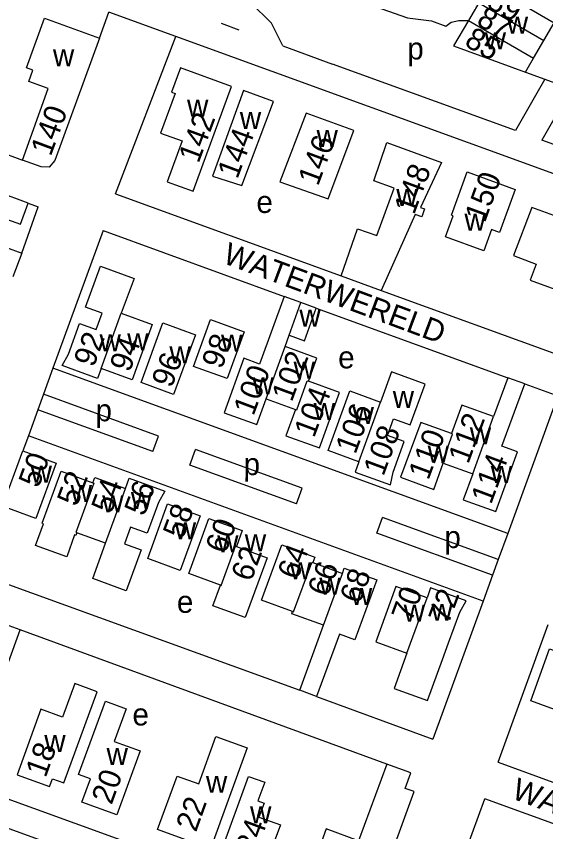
# Model space of a CAD drawing. Extents: x 154320 to 156262, y 382651 to 384180.
# Drawn here: x 156007.7 to 156103.4, y 383033.1 to 383180.7 of the extents above; entities that cross this region are included whole.
import ezdxf

# ---------------------------------------------------------------- set-up
doc = ezdxf.new("R2010")
doc.units = 0
for name, color, linetype in [('BLT_Basislijn', 7, 'Continuous'), ('BLT_Bebouwing', 7, 'Continuous'), ('BLT_Centroide', 7, 'Continuous'), ('BLT_Huisnummer', 7, 'Continuous'), ('BLT_Huisnummer_ tussenligend', 7, 'Continuous'), ('BLT_Onderverdeling_panden', 7, 'Continuous'), ('BLT_Plantopo', 7, 'Continuous'), ('BLT_Straatnaam', 7, 'Continuous')]:
    doc.layers.add(name, color=color, linetype=linetype)

msp = doc.modelspace()

# ---------------------------------------------------------------- linework, layer by layer
at = {"layer": 'BLT_Basislijn'}
for p, q in [((156022.72, 383176.68), (156024.45, 383181.39)), ((156036.57, 383176.99), (156024.45, 383181.39)), ((156047.98, 383178.16), (156044.79, 383179.32)), ((156025.65, 383148.51), (156036.57, 383176.99)), ((156118.43, 383147.22), (156036.57, 383176.99)), ((156055.87, 383175.29), (156064.86, 383172.02)), ((155963.09, 383171.24), (156008.81, 383154.64)), ((156099.75, 383170.56), (156103.25, 383169.28)), ((156103.25, 383169.28), (156097.97, 383159.98)), ((156103.25, 383169.28), (156108.02, 383167.55)), ((156108.02, 383167.55), (156102.73, 383158.25)), ((156025.65, 383148.51), (156066.46, 383133.71)), ((156009.83, 383146.86), (156011.63, 383146.15)), ((156008.68, 383137.82), (156011.63, 383146.15)), ((156023.38, 383141.88), (156014.32, 383116.97)), ((156023.38, 383141.88), (156056.14, 383129.95)), ((156073.69, 383131.02), (156108, 383118.56)), ((156061.92, 383127.86), (156096.6, 383115.25)), ((156014.32, 383116.97), (156012.62, 383112.28)), ((156096.56, 383087.08), (156014.32, 383116.97)), ((156099.63, 383114.14), (156105.61, 383111.98)), ((156012.62, 383112.28), (156011.59, 383109.46)), ((156033.43, 383104.71), (156012.62, 383112.28)), ((156105.61, 383111.98), (156096.56, 383087.08)), ((156011.59, 383109.46), (156009.88, 383104.76)), ((156032.41, 383101.89), (156011.59, 383109.46)), ((156009.88, 383104.76), (156008.87, 383102.02)), ((156092.11, 383074.86), (156009.88, 383104.76)), ((156032.41, 383101.89), (156033.43, 383104.71)), ((156039.1, 383099.45), (156040.13, 383102.27)), ((156059.4, 383095.26), (156040.13, 383102.27)), ((156058.38, 383092.45), (156039.1, 383099.45)), ((156058.38, 383092.45), (156059.4, 383095.26)), ((156072.92, 383087.16), (156073.95, 383089.98)), ((156094.85, 383082.38), (156073.95, 383089.98)), ((156093.82, 383079.56), (156072.92, 383087.16)), ((156096.56, 383087.08), (156094.85, 383082.38)), ((156094.85, 383082.38), (156093.82, 383079.56)), ((156000.83, 383079.85), (156058.97, 383058.73)), ((156093.82, 383079.56), (156092.11, 383074.86)), ((156092.11, 383074.86), (156083.02, 383049.84)), ((156094.81, 383045.68), (156103.86, 383070.59)), ((156074.68, 383045.34), (156008.37, 383069.63)), ((156062.01, 383057.59), (156083.02, 383049.84)), ((156082.33, 383011.38), (156092.41, 383039.1))]:
    msp.add_line(p, q, dxfattribs=at)
for points in [[(156053.63, 383189.1), (156063.31, 383185.56), (156068.94, 383184.05), (156070.37, 383183.18), (156078.47, 383180.38), (156082.76, 383179.81), (156085.39, 383178.84), (156086.36, 383179.59), (156087.7, 383179.88), (156089.47, 383179.91)], [(156055.87, 383175.29), (156053.84, 383179.39), (156050.04, 383183.15)], [(156097.97, 383159.98), (156064.86, 383172.02)], [(156200.85, 383089.67), (156203.15, 383094.62), (156204.46, 383100.24), (156204.4, 383106.02), (156203.12, 383111.67), (156200.54, 383116.84), (156196.98, 383121.3), (156192.54, 383124.94), (156187.68, 383127.36), (156102.73, 383158.25)], [(155988.35, 383045.55), (156070.59, 383015.65)], [(156094.81, 383045.68), (156114.6, 383038.49)], [(156150.87, 383017.85), (156092.41, 383039.1)], [(155997.68, 383036.84), (156068.88, 383010.95)]]:
    msp.add_lwpolyline(points, dxfattribs=at)
at = {"layer": 'BLT_Bebouwing'}
for p, q in [((156022.72, 383176.68), (156014.69, 383154.59)), ((156072.36, 383150.9), (156074.71, 383157.79)), ((156074.71, 383157.79), (156084.58, 383154.19)), ((156084.58, 383154.19), (156080.78, 383146.07)), ((156009.83, 383146.86), (155990.99, 383153.67)), ((156076.01, 383149.57), (156072.36, 383150.9)), ((156072.91, 383141), (156076.01, 383149.57)), ((156080.78, 383146.07), (156081.53, 383145.8)), ((156081.53, 383145.8), (156081.01, 383144.35)), ((156079.84, 383144.77), (156073.9, 383131.59)), ((156081.01, 383144.35), (156079.84, 383144.77)), ((156066.46, 383133.71), (156069.38, 383142.21)), ((156069.38, 383142.21), (156072.91, 383141)), ((156008.68, 383137.82), (156007.09, 383133.49)), ((156066.46, 383133.71), (156073.69, 383131.02)), ((156073.9, 383131.59), (156073.69, 383131.02)), ((156059.18, 383128.85), (156056.14, 383129.95)), ((156061.92, 383127.86), (156059.18, 383128.85)), ((156056.29, 383120.88), (156057.04, 383122.94)), ((156096.6, 383115.25), (156094, 383108.24)), ((156099.63, 383114.14), (156096.6, 383115.25)), ((156052.86, 383111.47), (156058.2, 383109.54)), ((156005.23, 383092.02), (156008.87, 383102.02)), ((156084.9, 383099.82), (156090.23, 383097.88)), ((156023.83, 383085.31), (156018.63, 383087.19)), ((156061.33, 383081.8), (156066.67, 383079.86)), ((156058.97, 383058.73), (156063.24, 383070.47)), ((156062.01, 383057.59), (156058.97, 383058.73))]:
    msp.add_line(p, q, dxfattribs=at)
for points in [[(156091.34, 383183.11), (156089.47, 383179.91)], [(156008.81, 383154.64), (156013.47, 383167.57), (156009.96, 383168.83), (156010.7, 383170.88), (156009.55, 383171.3), (156012.81, 383180.32), (156022.72, 383176.68)], [(156089.47, 383179.91), (156086.77, 383175.28), (156099.75, 383170.56)], [(156103.08, 383176.26), (156104.95, 383179.47)], [(156101.21, 383173.06), (156103.08, 383176.26)], [(156100.07, 383171.11), (156101.21, 383173.06)], [(156099.75, 383170.56), (156100.07, 383171.11)], [(156014.69, 383154.59), (156013.66, 383153.36), (156012.19, 383153.42), (156008.81, 383154.64)], [(155990.99, 383153.67), (155989.19, 383148.68), (155994.83, 383146.63), (155994.42, 383145.49), (156005.07, 383141.61), (156005.93, 383143.96), (156008.44, 383143.06), (156009.83, 383146.86)], [(156001.61, 383137.9), (156005.74, 383138.89), (156008.68, 383137.82)], [(156023.06, 383116.91), (156022.39, 383115.13), (156016.02, 383117.5), (156017.11, 383119.5), (156019.14, 383125.07), (156022.14, 383123.98), (156023.2, 383126.92), (156020.21, 383128.02), (156022.92, 383135.43), (156028.99, 383133.21), (156026.67, 383126.93)], [(156056.14, 383129.95), (156051.67, 383117.74), (156048.84, 383118.78), (156045.3, 383108.92), (156051.17, 383106.78), (156052.86, 383111.47)], [(156057.04, 383122.94), (156059.79, 383121.95), (156061.92, 383127.86)], [(156026.67, 383126.93), (156032.29, 383124.88), (156028.67, 383114.88), (156023.06, 383116.91)], [(156060.53, 383114.62), (156062.04, 383118.79), (156056.29, 383120.88)], [(156069.62, 383100.05), (156068.95, 383098.18), (156075.38, 383095.86), (156075.84, 383098.16), (156077.84, 383103.71), (156074.83, 383104.79), (156075.93, 383107.8), (156078.94, 383106.71), (156081.63, 383114.11), (156075.55, 383116.32), (156073.57, 383110.86)], [(156058.2, 383109.54), (156056.47, 383104.76), (156062.5, 383102.58), (156066.14, 383112.57), (156060.53, 383114.62)], [(156069.62, 383100.05), (156064.08, 383102.07), (156068.03, 383112.88), (156073.57, 383110.86)], [(156090.23, 383097.88), (156088.52, 383093.18), (156094.41, 383091.06), (156098.32, 383101.85), (156095.49, 383102.89), (156099.63, 383114.14)], [(156094, 383108.24), (156088.26, 383110.31), (156086.37, 383105.14)], [(156086.37, 383105.14), (156080.83, 383107.15), (156077.16, 383097.24), (156083.19, 383095.03), (156084.9, 383099.82)], [(156008.87, 383102.02), (156014.88, 383099.83), (156011.22, 383089.81), (156005.23, 383092.02)], [(156018.63, 383087.19), (156018.46, 383086.74), (156018.23, 383086.83), (156016.82, 383082.85), (156011.19, 383084.91), (156012.62, 383088.85), (156012.4, 383088.94), (156015.81, 383098.35), (156021.55, 383096.26)], [(156027.44, 383095.19), (156028.12, 383097.07), (156034.54, 383094.74), (156033.42, 383092.68), (156031.38, 383087.11), (156028.37, 383088.21), (156027.29, 383085.23), (156030.29, 383084.14), (156027.59, 383076.73), (156021.53, 383078.93), (156023.83, 383085.31)], [(156021.55, 383096.26), (156021.89, 383097.2), (156027.44, 383095.19)], [(156044.6, 383077.72), (156038.91, 383079.83), (156042.53, 383089.79), (156048.53, 383087.59), (156047.49, 383084.71)], [(156047.49, 383084.71), (156053.05, 383082.68), (156049.11, 383071.89), (156043.25, 383074.01), (156044.6, 383077.72)], [(156057.65, 383072.95), (156052.03, 383074.99), (156055.69, 383085), (156061.7, 383082.81), (156061.33, 383081.8)], [(156066.67, 383079.86), (156067.01, 383080.8), (156072.88, 383078.67), (156068.93, 383067.85), (156066.13, 383068.88), (156062.01, 383057.59)], [(156081.97, 383075.45), (156076.35, 383077.49), (156072.72, 383067.48), (156078.32, 383065.44)], [(156078.32, 383065.44), (156076.01, 383059.04), (156082.08, 383056.85), (156084.8, 383064.3), (156085.87, 383067.29), (156087.9, 383072.84), (156089.04, 383074.88), (156082.63, 383077.25), (156081.97, 383075.45)], [(156008.37, 383069.63), (155998.4, 383073.25), (155992.01, 383055.71)], [(156063.24, 383070.47), (156057.51, 383072.55), (156057.65, 383072.95)], [(155992.01, 383055.71), (155993.34, 383055.23), (155991.01, 383048.81), (156000.58, 383045.34), (156003.68, 383053.86), (156002.17, 383054.41), (156003.47, 383057.94), (155999.89, 383059.25), (156002.11, 383065.33), (156006.26, 383063.82), (156008.37, 383069.63)], [(156106.97, 383055.03), (156106.81, 383054.6), (156100.73, 383056.83), (156104.15, 383066.23), (156109.82, 383064.17)], [(156074.68, 383045.34), (156072.63, 383039.78), (156069.59, 383031.5), (156063.75, 383033.65), (156061.6, 383027.81), (156065.94, 383026.24), (156064.44, 383022.13), (156071.98, 383019.37)], [(156071.98, 383019.37), (156079.66, 383040.37), (156078, 383040.97), (156079.02, 383043.76), (156074.68, 383045.34)], [(156049.71, 383043.14), (156052.62, 383042.07), (156051.36, 383038.69), (156052.51, 383038.27), (156051.58, 383035.78), (156055.45, 383034.34), (156052.51, 383026.45), (156044.68, 383029.37), (156049.71, 383043.14)]]:
    msp.add_lwpolyline(points, dxfattribs=at)
for points in [[(156037.37, 383171.34), (156035.78, 383166.93), (156036.41, 383166.7), (156033.8, 383159.52), (156037.68, 383158.1), (156035, 383150.7), (156039.71, 383148.99), (156046.61, 383167.97)], [(156048.77, 383167.24), (156043.16, 383151.73), (156048.46, 383150.03), (156054.24, 383165.21)], [(156060.11, 383163.12), (156055.37, 383150.7), (156064.12, 383147.65), (156068.74, 383160)], [(156089.21, 383152.5), (156097.93, 383149.32), (156095.06, 383141.53), (156093.63, 383142.05), (156092.22, 383138.22), (156085.3, 383140.74), (156086.69, 383144.58), (156086.37, 383144.7)], [(156034.21, 383125.18), (156040.08, 383123.04), (156036.14, 383112.23), (156030.27, 383114.38)], [(156042.81, 383125.78), (156048.89, 383123.56), (156045.81, 383115.1), (156039.73, 383117.32)], [(156035.05, 383092.42), (156040.93, 383090.29), (156037.33, 383080.41), (156031.47, 383082.55)], [(156012.16, 383055.27), (156007.84, 383043.4), (156013.73, 383041.29), (156014.24, 383042.71), (156016.29, 383041.96), (156022.3, 383058.46), (156018.27, 383059.92), (156016.05, 383053.86)], [(156023.81, 383056.76), (156027.57, 383055.38), (156025.38, 383049.42), (156030.1, 383047.73), (156025.9, 383036.16), (156019.58, 383038.44), (156021.14, 383042.69), (156018.97, 383043.48)], [(156036.76, 383043.2), (156040.68, 383041.8), (156043.79, 383050.35), (156049.47, 383048.31), (156042.8, 383030.01), (156033.25, 383033.54)]]:
    msp.add_lwpolyline(points, close=True, dxfattribs=at)
at = {"layer": 'BLT_Onderverdeling_panden'}
for p, q in [((156057.04, 383122.94), (156059.18, 383128.85)), ((156023.06, 383116.91), (156026.67, 383126.93)), ((156052.86, 383111.47), (156056.29, 383120.88)), ((156069.62, 383100.05), (156073.57, 383110.86)), ((156090.23, 383097.88), (156094, 383108.24)), ((156023.83, 383085.31), (156027.44, 383095.19)), ((156063.24, 383070.47), (156066.67, 383079.86)), ((156078.32, 383065.44), (156081.97, 383075.45))]:
    msp.add_line(p, q, dxfattribs=at)
for points in [[(156093.21, 383186.32), (156104.95, 383179.47)], [(156091.34, 383183.11), (156103.08, 383176.26)], [(156089.47, 383179.91), (156101.21, 383173.06)], [(156058.2, 383109.54), (156058.42, 383109.46), (156060.32, 383114.69), (156060.53, 383114.62)], [(156084.9, 383099.82), (156084.71, 383099.88), (156086.56, 383105.07), (156086.37, 383105.14)], [(156021.55, 383096.26), (156021.71, 383096.2), (156018.46, 383087.25), (156018.63, 383087.19)], [(156044.6, 383077.72), (156044.75, 383077.67), (156047.34, 383084.76), (156047.49, 383084.71)], [(156057.65, 383072.95), (156057.85, 383072.88), (156061.13, 383081.86), (156061.33, 383081.8)]]:
    msp.add_lwpolyline(points, dxfattribs=at)
at = {"layer": 'BLT_Plantopo'}
msp.add_lwpolyline([(156116.31, 383141.85), (156114.58, 383142.48), (156114.85, 383143.22), (156112.95, 383143.92), (156112.68, 383143.19), (156110.8, 383143.88), (156111, 383144.44), (156105.58, 383146.43), (156104.91, 383144.6), (156100.93, 383146.04), (156097.6, 383137.35), (156101.68, 383135.83), (156100.62, 383132.94), (156111.55, 383128.92)], close=True, dxfattribs=at)

# ---------------------------------------------------------------- texts
at = {"layer": 'BLT_Centroide'}
for s, p in [('w', (156096.39, 383177.51)), ('w', (156092.39, 383174.66)), ('w', (156014.32, 383171.62)), ('p', (156078.4, 383172.83)), ('w', (156038.57, 383162.49)), ('w', (156048.12, 383160.26)), ('w', (156061.99, 383157.02)), ('e', (156051.12, 383145.07)), ('w', (156076.41, 383146.34)), ('w', (156088.74, 383141.85)), ('w', (156058.88, 383124.52)), ('w', (156022.75, 383120.06)), ('w', (156027.75, 383120.22)), ('w', (156044.72, 383119.97)), ('w', (156035.39, 383117.84)), ('e', (156065.9, 383116.95)), ('w', (156057.84, 383115.08)), ('w', (156050.39, 383112.25)), ('w', (156075.77, 383109.81)), ('w', (156061.47, 383107.59)), ('w', (156068.51, 383106.91)), ('w', (156089.7, 383103.22)), ('w', (156082.08, 383099.92)), ('w', (156010.28, 383096.25)), ('w', (156093.5, 383096.2)), ('w', (156017.52, 383092.75)), ('w', (156023.23, 383090.89)), ('w', (156028.41, 383091.53)), ('w', (156036.34, 383086)), ('w', (156044.02, 383083.69)), ('w', (156049.02, 383083.84)), ('w', (156057.14, 383078.8)), ('w', (156062.5, 383076)), ('e', (156036.74, 383072.72)), ('w', (156068.2, 383074.14)), ('w', (156082.75, 383071.28)), ('w', (156077.75, 383071.12)), ('e', (156028.7, 383052.35)), ('w', (156012.76, 383047.55)), ('w', (156024.02, 383045.18)), ('w', (156041.99, 383040.16)), ('w', (156049.97, 383034.62))]:
    msp.add_text(s, height=4, dxfattribs=at).set_placement(p)
for p in [(156022.01, 383107.39), (156048.79, 383097.65), (156085.1, 383084.45)]:
    msp.add_text('p', height=4, rotation=359.5, dxfattribs=at).set_placement(p)
at = {"layer": 'BLT_Huisnummer'}
for s, rotation, p in [('89', 330.2347, (156092.51, 383182.42)), ('85', 330.2347, (156088.53, 383175.45)), ('140', 69.5777, (156013.92, 383155.18)), ('142', 69.5777, (156040.65, 383153.91)), ('144', 69.5777, (156047.68, 383151.07)), ('146', 69.5777, (156062.26, 383149.81)), ('148', 69.5777, (156079.63, 383144.62)), ('150', 70.0195, (156092.43, 383143.16)), ('92', 69.5774, (156021.7, 383117)), ('96', 69.5774, (156035.79, 383113.27)), ('100', 69.5774, (156050.58, 383108.21)), ('104', 69.5774, (156061.55, 383104.25)), ('108', 69.5774, (156074.08, 383097.3)), ('50', 69.5774, (156011.71, 383095.16)), ('114', 69.5774, (156093.55, 383092.2)), ('54', 69.5774, (156024.86, 383090.49)), ('58', 69.5774, (156037.81, 383085.92)), ('62', 69.5774, (156050.16, 383078.21)), ('66', 69.5774, (156063.98, 383075.48)), ('72', 69.5774, (156085.83, 383070.52)), ('18', 70.0193, (156013, 383042.75)), ('20', 70.0189, (156024.93, 383037.86)), ('22', 70.0188, (156040.19, 383032.91)), ('24', 69.5777, (156050.94, 383028.89))]:
    msp.add_text(s, height=4, rotation=rotation, dxfattribs=at).set_placement(p)
at = {"layer": 'BLT_Huisnummer_ tussenligend'}
for s, rotation, p in [('87', 330.2347, (156090.69, 383179.25)), ('98', 69.5774, (156044.84, 383116.66)), ('94', 69.5774, (156028.19, 383116.09)), ('102', 69.5774, (156057.51, 383110.73)), ('106', 69.5774, (156069.02, 383101.27)), ('112', 69.5774, (156089.42, 383099.51)), ('110', 69.5774, (156082.22, 383096.59)), ('52', 69.5774, (156018.66, 383091.81)), ('56', 69.5774, (156030.83, 383090.07)), ('60', 69.5774, (156045.51, 383083.24)), ('64', 69.5774, (156058.54, 383078.55)), ('68', 69.5774, (156069.82, 383074.21)), ('70', 69.5774, (156079.15, 383070.95))]:
    msp.add_text(s, height=4, rotation=rotation, dxfattribs=at).set_placement(p)
at = {"layer": 'BLT_Straatnaam'}
for p in [(156044.83, 383136.08), (156097.07, 383039.21)]:
    msp.add_text('WATERWERELD', height=4, rotation=339.5777, dxfattribs=at).set_placement(p)

doc.saveas('drawing.dxf')
